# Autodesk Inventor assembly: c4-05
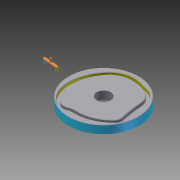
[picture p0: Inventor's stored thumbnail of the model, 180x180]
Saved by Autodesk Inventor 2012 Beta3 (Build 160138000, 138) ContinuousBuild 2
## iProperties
Created: 2010-11
Part Number: c4-05
Document SubType Name: Assembly
Designer: Beta-8540w
Author: Beta-8540w
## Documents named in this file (3)
- C:\Inventor 2012 Essentials\Assemblies\Chapter 4\c4-05.iam
- C:\Inventor 2012 Essentials\Parts\Chapter 4\c4-05.ipt
- C:\Inventor 2012 Essentials\Parts\Chapter 4\c4-06.ipt
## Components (2 placed, 2 different names)
1. c4-05:1 — Mate:1
2. c4-06:1 — Mate:1
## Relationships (1: Mate 1)
- Mate:1: c4-05:1 ↔ c4-06:1
